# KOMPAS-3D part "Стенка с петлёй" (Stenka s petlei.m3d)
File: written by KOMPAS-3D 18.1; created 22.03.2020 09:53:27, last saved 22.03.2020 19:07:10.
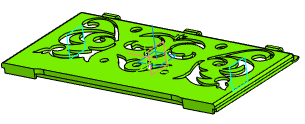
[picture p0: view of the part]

Document properties: Автор: windwican@hotmail.com; Полное имя файла: C:\Users\windw\Desktop\shkatilka1\bez petli\Измененная\Stenka s petlei.m3d

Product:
- Part/product: Стенка с петлёй
    Масса: 5.41403

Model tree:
1. Эскиз:1
2. Элемент выдавливания:2
     Расстояние 1 = 6
3. Эскиз:2  (with: Элемент выдавливания:2)
4. Элемент выдавливания:3
     Расстояние 1 = 10
5. Скругление:3  (with: Элемент выдавливания:3)
     Радиус = 3
6. Скругление:4  (with: Элемент выдавливания:2)
     Радиус = 1
7. Скругление:5  (with: Элемент выдавливания:2)
     Радиус = 2
8. Эскиз:3  (with: Элемент выдавливания:2)
9. Элемент выдавливания:4
     Толщина стенки 1 = 4; Расстояние 1 = 15; Расстояние 2 = 15
10. Смещенная плоскость:1
     Расстояние = 190
11. Эскиз:4  (with: Элемент выдавливания:2)
12. Элемент выдавливания:5
     Толщина стенки 1 = 4; Расстояние 1 = 15; Расстояние 2 = 15
13. Смещенная плоскость:2
     Расстояние = 190
14. Эскиз:5  (with: Элемент выдавливания:2)
15. Элемент выдавливания:6
     Толщина стенки 1 = 4; Расстояние 1 = 15; Расстояние 2 = 15
16. Скругление:8  (with: Элемент выдавливания:3)
     Радиус = 3
17. Скругление:9  (with: Элемент выдавливания:3)
     Радиус = 3
18. Скругление:10  (with: Элемент выдавливания:3)
     Радиус = 3
19. Скругление:11  (with: Элемент выдавливания:3)
     Радиус = 3
20. Эскиз:6  (with: Элемент выдавливания:2, Элемент выдавливания:4, Элемент выдавливания:5, Элемент выдавливания:6)
21. Эскиз:7  (with: Элемент выдавливания:6, Элемент выдавливания:2)
22. Элемент выдавливания:7
     Расстояние 2 = 30
23. Эскиз:8  (with: Элемент выдавливания:4)
24. Эскиз:9  (with: Элемент выдавливания:5)
25. Элемент выдавливания:8
     Расстояние 2 = 30
26. Элемент выдавливания:9
     Расстояние 2 = 30
27. Эскиз:10  (with: Элемент выдавливания:5, Элемент выдавливания:2)
28. Элемент выдавливания:10
     Толщина стенки 2 = 2; Расстояние 1 = 35; Расстояние 2 = 457.513
29. Эскиз:11  (with: Элемент выдавливания:5, Элемент выдавливания:8, Элемент выдавливания:10)
30. Элемент выдавливания:11
     Расстояние 2 = 30
31. Эскиз:12  (with: Элемент выдавливания:4)
32. Элемент выдавливания:12
     Расстояние 2 = 30
33. Эскиз:13  (with: Элемент выдавливания:6)
34. Элемент выдавливания:13
     Расстояние 2 = 30
35. Элемент выдавливания:14  (with: Элемент выдавливания:2)
     Расстояние 1 = 4.4
36. Скругление:14  (with: Элемент выдавливания:14)
     Радиус = 5
37. Скругление:15  (with: Скругление:14)
     Радиус = 5
38. Элемент выдавливания:15  (with: Элемент выдавливания:2)
     Расстояние 2 = 5
39. Скругление:16  (with: Элемент выдавливания:14)
     Полуось 1 = 1; Хорда = 7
